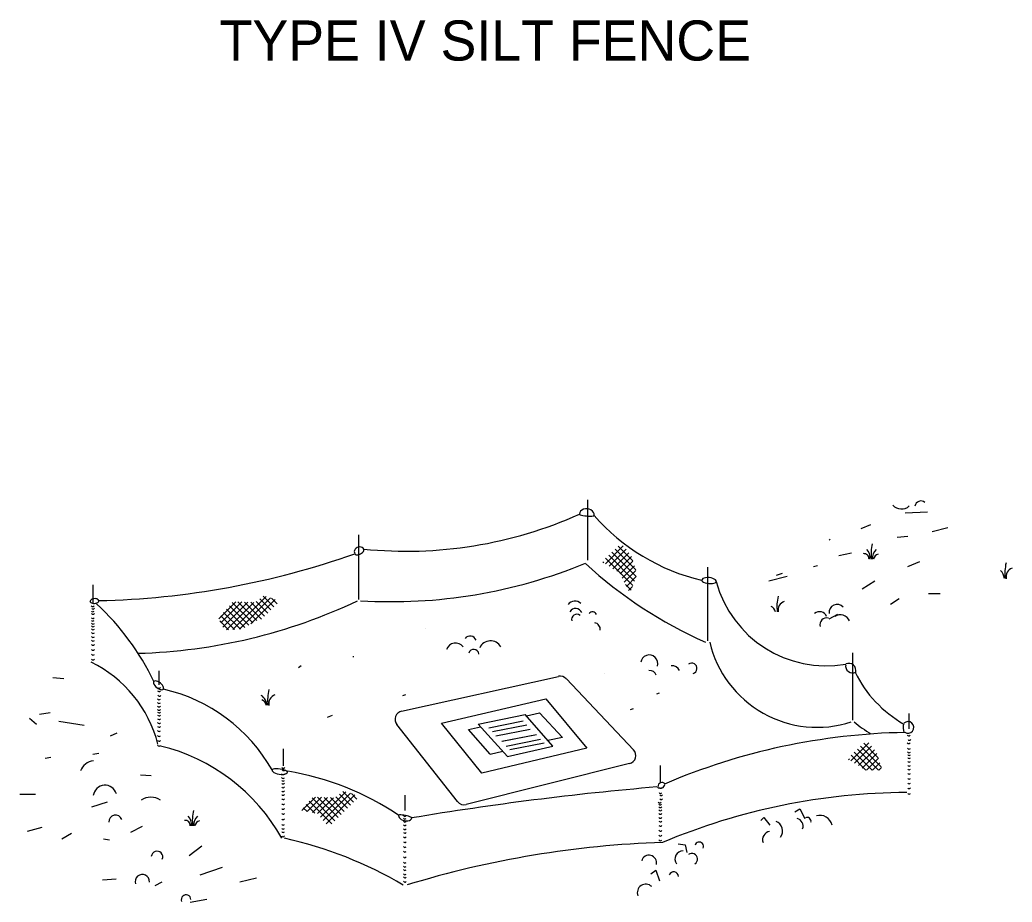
# Model space of a CAD drawing. Extents: x 539344 to 540004, y 1574686 to 1575110.
# Drawn here: x 539459.9 to 539578.4, y 1574893.2 to 1574998.7 of the extents above; entities that cross this region are included whole.
import ezdxf

# ---------------------------------------------------------------- set-up
doc = ezdxf.new("R2010")
doc.units = 0
doc.layers.add('Default', color=7, linetype='Continuous')
doc.layers.add('TextLabel', color=7, linetype='Continuous')

msp = doc.modelspace()

# ---------------------------------------------------------------- linework, layer by layer
at = {"layer": 'Default'}
for p, q in [((539527.75, 1574934.14), (539527.75, 1574941.35)), ((539565.65, 1574939.8), (539568.33, 1574939.91)), ((539560.42, 1574937.93), (539561.58, 1574938.4)), ((539568.91, 1574937.58), (539570.77, 1574938.05)), ((539500.38, 1574929.43), (539500.38, 1574937.18)), ((539556.58, 1574936.54), (539556.69, 1574936.65)), ((539564.72, 1574936.89), (539566, 1574937)), ((539531.99, 1574935.85), (539529.84, 1574933.7)), ((539532.33, 1574935.44), (539530.3, 1574933.41)), ((539530.62, 1574935.09), (539533.52, 1574932.19)), ((539532.66, 1574935.03), (539530.75, 1574933.12)), ((539531, 1574935.45), (539533.47, 1574932.98)), ((539531.38, 1574935.81), (539533.12, 1574934.07)), ((539557.74, 1574934.68), (539559.25, 1574935.02)), ((539529.55, 1574933.94), (539529.66, 1574933.82)), ((539529.86, 1574934.36), (539533.13, 1574931.1)), ((539530.24, 1574934.72), (539533.32, 1574931.64)), ((539532.96, 1574934.59), (539531.2, 1574932.83)), ((539533.14, 1574934.02), (539531.61, 1574932.5)), ((539566, 1574933.4), (539567.4, 1574933.98)), ((539533.32, 1574933.46), (539531.86, 1574932)), ((539533.5, 1574932.9), (539532.1, 1574931.51)), ((539542.08, 1574924.5), (539542.08, 1574933.32)), ((539550.29, 1574932.35), (539550.99, 1574932.58)), ((539554.72, 1574933.4), (539555.18, 1574933.51)), ((539533.52, 1574932.18), (539532.35, 1574931.01)), ((539549.36, 1574931.65), (539551.57, 1574932.23)), ((539560.53, 1574930.72), (539562.05, 1574931.65)), ((539468.64, 1574929), (539468.64, 1574931.19)), ((539532.24, 1574931.24), (539532.93, 1574930.55)), ((539533.1, 1574931.01), (539532.6, 1574930.52)), ((539485.68, 1574929.16), (539483.64, 1574927.12)), ((539486.4, 1574929.14), (539483.89, 1574926.63)), ((539487.12, 1574929.11), (539484.14, 1574926.14)), ((539487.84, 1574929.09), (539484.56, 1574925.81)), ((539485.27, 1574929.08), (539487.7, 1574926.64)), ((539489.3, 1574929.81), (539485.33, 1574925.84)), ((539485.94, 1574929.15), (539488.18, 1574926.91)), ((539489.85, 1574929.62), (539486.11, 1574925.88)), ((539486.71, 1574929.13), (539488.76, 1574927.08)), ((539487.47, 1574929.1), (539489.13, 1574927.45)), ((539490.4, 1574929.43), (539487.5, 1574926.53)), ((539488.12, 1574929.19), (539489.5, 1574927.82)), ((539488.55, 1574929.51), (539489.87, 1574928.19)), ((539488.97, 1574929.83), (539490.24, 1574928.56)), ((539489.97, 1574929.58), (539490.61, 1574928.93)), ((539563.91, 1574928.86), (539564.96, 1574929.56)), ((539568.45, 1574930.14), (539569.84, 1574930.14)), ((539484.23, 1574927.89), (539486.24, 1574925.88)), ((539484.58, 1574928.29), (539486.76, 1574926.1)), ((539484.92, 1574928.68), (539487.23, 1574926.37)), ((539483.76, 1574926.88), (539484.82, 1574925.82)), ((539483.88, 1574927.5), (539485.53, 1574925.85)), ((539556.58, 1574927.11), (539557.62, 1574927.69)), ((539508.4, 1574925.95), (539508.4, 1574925.95)), ((539559.41, 1574915.01), (539559.41, 1574923.08)), ((539499.79, 1574922.57), (539499.68, 1574922.57)), ((539476.53, 1574919.23), (539476.53, 1574920.91)), ((539493.16, 1574921.29), (539493.51, 1574921.53)), ((539463.84, 1574920.13), (539465.12, 1574920.01)), ((539505.5, 1574916.09), (539524.24, 1574920.25)), ((539525.18, 1574919.96), (539533.21, 1574911.47)), ((539529.7, 1574920.6), (539529.7, 1574920.6)), ((539505.96, 1574918.04), (539505.61, 1574917.92)), ((539510.25, 1574914.67), (539522.74, 1574917.56)), ((539522.74, 1574917.56), (539527.64, 1574911.65)), ((539535.98, 1574918.15), (539536.33, 1574918.27)), ((539462.21, 1574915.71), (539463.49, 1574915.94)), ((539532.84, 1574916.29), (539533.19, 1574916.41)), ((539461.04, 1574915.24), (539461.86, 1574914.55)), ((539464.53, 1574914.89), (539467.56, 1574914.43)), ((539496.65, 1574915.36), (539497.23, 1574915.59)), ((539514.65, 1574914.54), (539520.25, 1574915.7)), ((539515.92, 1574914.11), (539520.03, 1574914.92)), ((539523.56, 1574911.92), (539520.25, 1574915.7)), ((539520.41, 1574915.52), (539521.96, 1574915.87)), ((539524.74, 1574912.92), (539521.96, 1574915.87)), ((539566.16, 1574913.97), (539566.16, 1574915.81)), ((539512.18, 1574905.27), (539504.93, 1574914.5)), ((539515.1, 1574908.66), (539510.25, 1574914.67)), ((539513.47, 1574913.9), (539514.94, 1574914.22)), ((539516.07, 1574910.96), (539513.47, 1574913.9)), ((539518.14, 1574910.68), (539514.65, 1574914.54)), ((539516.36, 1574913.67), (539520.47, 1574914.47)), ((539516.75, 1574913.13), (539520.86, 1574913.94)), ((539470.7, 1574913.15), (539471.52, 1574913.5)), ((539517.49, 1574912.5), (539521.6, 1574913.3)), ((539517.51, 1574912.5), (539521.62, 1574913.3)), ((539517.98, 1574911.91), (539522.09, 1574912.72)), ((539524.74, 1574912.92), (539522.97, 1574912.59)), ((539491.37, 1574909.53), (539491.37, 1574911.59)), ((539527.64, 1574911.65), (539515.1, 1574908.66)), ((539516.07, 1574910.96), (539517.59, 1574911.29)), ((539518.14, 1574910.68), (539523.56, 1574911.92)), ((539518.43, 1574911.49), (539522.54, 1574912.3)), ((539561.33, 1574912.3), (539559.18, 1574910.15)), ((539561.66, 1574911.89), (539559.63, 1574909.86)), ((539559.96, 1574911.53), (539562.46, 1574909.03)), ((539562, 1574911.48), (539560.08, 1574909.57)), ((539560.33, 1574911.9), (539562.8, 1574909.43)), ((539560.71, 1574912.26), (539562.45, 1574910.52)), ((539462.91, 1574910.47), (539463.6, 1574910.59)), ((539468.61, 1574910.94), (539469.31, 1574911.05)), ((539558.88, 1574910.38), (539558.99, 1574910.27)), ((539559.2, 1574910.81), (539560.97, 1574909.03)), ((539559.58, 1574911.17), (539561.71, 1574909.03)), ((539562.29, 1574911.03), (539560.53, 1574909.27)), ((539562.47, 1574910.47), (539561.03, 1574909.03)), ((539532.73, 1574909.81), (539513.21, 1574904.92)), ((539536.42, 1574907.61), (539536.42, 1574909.57)), ((539562.65, 1574909.91), (539561.78, 1574909.03)), ((539562.83, 1574909.35), (539562.52, 1574909.03)), ((539474.31, 1574908.49), (539475.59, 1574908.38)), ((539498.82, 1574906.46), (539495.79, 1574903.43)), ((539498.49, 1574906.48), (539499.76, 1574905.21)), ((539459.88, 1574906.17), (539461.74, 1574906.17)), ((539495.2, 1574905.81), (539493.59, 1574904.2)), ((539495.92, 1574905.79), (539494.21, 1574904.08)), ((539494.44, 1574905.33), (539497.16, 1574902.61)), ((539494.79, 1574905.73), (539497.53, 1574902.98)), ((539496.64, 1574905.76), (539494.84, 1574903.96)), ((539497.36, 1574905.74), (539495.45, 1574903.84)), ((539495.46, 1574905.8), (539497.91, 1574903.36)), ((539499.37, 1574906.27), (539496.13, 1574903.03)), ((539496.23, 1574905.78), (539498.28, 1574903.73)), ((539499.92, 1574906.08), (539496.47, 1574902.63)), ((539496.99, 1574905.75), (539498.65, 1574904.1)), ((539497.64, 1574905.84), (539499.02, 1574904.47)), ((539498.07, 1574906.16), (539499.39, 1574904.84)), ((539499.49, 1574906.23), (539500.13, 1574905.58)), ((539505.91, 1574904.19), (539505.91, 1574906.05)), ((539468.49, 1574904.65), (539470.35, 1574905.24)), ((539493.75, 1574904.54), (539494.21, 1574904.08)), ((539494.1, 1574904.94), (539495.12, 1574903.91)), ((539552.5, 1574904.07), (539553.09, 1574904.42)), ((539553.09, 1574904.42), (539553.67, 1574903.26)), ((539548.43, 1574903.03), (539548.78, 1574903.37)), ((539548.78, 1574903.37), (539549.48, 1574902.44)), ((539460.81, 1574901.75), (539462.56, 1574902.21)), ((539473.15, 1574901.63), (539474.54, 1574902.33)), ((539464.88, 1574900.81), (539466.05, 1574901.51)), ((539469.89, 1574900.81), (539470.59, 1574900.7)), ((539480.13, 1574898.84), (539481.64, 1574900)), ((539538.54, 1574900.23), (539539.36, 1574900.12)), ((539539.36, 1574900.12), (539539.59, 1574899.19)), ((539481.41, 1574896.51), (539484.08, 1574897.44)), ((539535.28, 1574896.63), (539535.86, 1574897.09)), ((539535.86, 1574897.09), (539536.33, 1574895.81)), ((539469.77, 1574895.93), (539471.4, 1574896.04)), ((539486.18, 1574895.69), (539488.16, 1574896.16)), ((539476.05, 1574895.23), (539476.87, 1574895.69)), ((539480.24, 1574893.25), (539482.22, 1574893.6))]:
    msp.add_line(p, q, dxfattribs=at)
for centre, radius, start, end in [((539567.56, 1574940.47), 0.748, 50.6366, 169.3296), ((539565.23, 1574941.66), 1.4, 221.8186, 311.8186), ((539506.03, 1574985.91), 50.7, 264.2704, 294.1119), ((539546.97, 1574955.61), 24.52, 221.1263, 256.7442), ((539567.08, 1574934.87), 5.49, 166.9838, 186.4492), ((539560.73, 1574934.3), 0.621, 356.1525, 95.6419), ((539559.98, 1574934.41), 1.51, 354.036, 42.1941), ((539563.2, 1574934.37), 1.44, 134.0218, 184.6697), ((539467.12, 1575027.5), 98.22, 271.2713, 289.4914), ((539504.29, 1574989.88), 60.7, 266.5, 292.4426), ((539563.68, 1574973.26), 53.61, 227.5042, 245.9018), ((539562.67, 1574934.12), 0.782, 106.1258, 170.1309), ((539583.07, 1574932.57), 5.49, 166.9838, 186.4492), ((539575.83, 1574931.74), 1.7, 6.9894, 43.2163), ((539578.83, 1574932.14), 1.11, 109.8004, 191.1102), ((539556.22, 1574935.11), 13.6, 195.0648, 279.9146), ((539472.17, 1574988.59), 65.61, 271.6049, 295.3312), ((539526.2, 1574928.22), 1.03, 45.8458, 142.3307), ((539555.83, 1574928.59), 5.49, 166.9838, 186.4492), ((539551.59, 1574928.16), 1.11, 109.8004, 191.1102), ((539468.58, 1574928.79), 0.201, 209.3925, 323.8148), ((539468.6, 1574928.18), 0.201, 209.3925, 323.8148), ((539468.64, 1574928.5), 0.201, 209.3925, 323.8148), ((539448.35, 1574906.49), 30.52, 25.4833, 47.2792), ((539526.29, 1574927.56), 0.801, 22.2509, 149.0252), ((539528.32, 1574927.47), 0.496, 19.5572, 146.1768), ((539549.34, 1574927.82), 0.844, 9.5904, 69.4639), ((539555.45, 1574927.09), 0.89, 21.4734, 132.5198), ((539557.53, 1574927.91), 0.944, 40.415, 189.5884), ((539468.6, 1574927.36), 0.201, 209.3925, 323.8148), ((539468.6, 1574927.05), 0.201, 209.3925, 323.8148), ((539468.62, 1574927.87), 0.201, 209.3925, 323.8148), ((539526.43, 1574927.04), 0.627, 52.125, 195.2551), ((539528.46, 1574925.88), 0.776, 351.7969, 82.0054), ((539556.27, 1574926.43), 0.8, 74.0792, 195.9208), ((539557.92, 1574926.44), 1.18, 21.2965, 123.9769), ((539468.62, 1574926.69), 0.201, 209.3925, 323.8148), ((539468.62, 1574926.38), 0.201, 209.3925, 323.8148), ((539468.62, 1574926.02), 0.201, 209.3925, 323.8148), ((539468.62, 1574925.58), 0.201, 209.3925, 323.8148), ((539468.62, 1574925.11), 0.201, 209.3925, 323.8148), ((539468.62, 1574924.67), 0.201, 209.3925, 323.8148), ((539513.67, 1574924.3), 0.77, 20.2635, 140.7978), ((539516.12, 1574923.06), 1.43, 30.5601, 154.4229), ((539555.16, 1574927.36), 13.2, 193.2831, 287.9059), ((539468.62, 1574924.16), 0.201, 209.3925, 323.8148), ((539468.62, 1574923.56), 0.201, 209.3925, 323.8148), ((539511.95, 1574923.09), 1.14, 37.8709, 161.0162), ((539514.11, 1574922.85), 0.619, 6.0711, 163.5315), ((539461.72, 1574908.36), 15.14, 14.4282, 63.7692), ((539468.62, 1574922.99), 0.201, 209.3925, 323.8148), ((539468.62, 1574922.41), 0.201, 209.3925, 323.8148), ((539535.08, 1574921.79), 1.02, 342.6112, 172.3067), ((539535.17, 1574920.14), 0.8, 17.6711, 98.3533), ((539537.87, 1574920.63), 0.874, 20.5809, 101.3099), ((539540.17, 1574921.21), 0.627, 285.2308, 127.8159), ((539559.37, 1574921.49), 0.823, 169.307, 297.603), ((539558.92, 1574920.94), 0.866, 344.9997, 114.1316), ((539572.73, 1574927.19), 14.56, 206.2944, 240.2561), ((539524.45, 1574919.28), 1, 43.4045, 102.5237), ((539476.51, 1574918.63), 0.201, 209.3925, 323.8148), ((539476.53, 1574919.02), 0.201, 209.3925, 323.8148), ((539472.65, 1574899.26), 19.94, 29.4453, 77.3064), ((539494.98, 1574917.42), 5.49, 166.9838, 186.4492), ((539476.51, 1574917.65), 0.201, 209.3925, 323.8148), ((539476.55, 1574918.08), 0.201, 209.3925, 323.8148), ((539487.73, 1574916.6), 1.7, 6.9894, 53.8757), ((539488.49, 1574916.65), 0.844, 9.5904, 69.4639), ((539490.73, 1574916.99), 1.11, 109.8004, 191.1102), ((539476.51, 1574917.22), 0.201, 209.3925, 323.8148), ((539476.51, 1574916.79), 0.201, 209.3925, 323.8148), ((539476.51, 1574916.39), 0.201, 209.3925, 323.8148), ((539476.52, 1574916.08), 0.201, 209.3925, 323.8148), ((539505.72, 1574915.11), 1, 102.5229, 218.1397), ((539476.52, 1574915.72), 0.201, 209.3925, 323.8148), ((539476.52, 1574915.28), 0.201, 209.3925, 323.8148), ((539568.52, 1574925.43), 13.9, 229.9052, 240.0298), ((539566.01, 1574914.14), 0.693, 234.7925, 134.7168), ((539476.52, 1574914.81), 0.201, 209.3925, 323.8148), ((539476.52, 1574914.37), 0.201, 209.3925, 323.8148), ((539476.52, 1574913.86), 0.201, 209.3925, 323.8148), ((539567.7, 1574914.18), 2.27, 170.0354, 196.5746), ((539476.52, 1574913.26), 0.201, 209.3925, 323.8148), ((539476.52, 1574912.69), 0.201, 209.3925, 323.8148), ((539567.02, 1574836.99), 76.56, 91.0489, 113.1754), ((539566.09, 1574913.33), 0.201, 209.3925, 323.8148), ((539566.18, 1574912.8), 0.201, 209.3925, 323.8148), ((539476.52, 1574912.11), 0.201, 209.3925, 323.8148), ((539471.32, 1574889.82), 22.74, 29.1555, 76.3774), ((539532.49, 1574910.78), 1, 284.0719, 43.4024), ((539566.09, 1574912.41), 0.201, 209.3925, 323.8148), ((539566.13, 1574911.75), 0.201, 209.3925, 323.8148), ((539566.13, 1574911.31), 0.201, 209.3925, 323.8148), ((539468.92, 1574908.25), 1.93, 97.697, 158.6536), ((539566.14, 1574910.99), 0.201, 209.3925, 323.8148), ((539566.14, 1574910.63), 0.201, 209.3925, 323.8148), ((539566.14, 1574910.2), 0.201, 209.3925, 323.8148), ((539491.37, 1574909.46), 0.201, 209.3925, 323.8148), ((539491.4, 1574909.18), 0.201, 209.3925, 323.8148), ((539486.35, 1574875.78), 33.6, 55.9783, 80.4814), ((539566.14, 1574909.72), 0.201, 209.3925, 323.8148), ((539566.14, 1574909.28), 0.201, 209.3925, 323.8148), ((539491.34, 1574908.7), 0.201, 209.3925, 323.8148), ((539491.34, 1574908.25), 0.201, 209.3925, 323.8148), ((539491.35, 1574907.93), 0.201, 209.3925, 323.8148), ((539566.14, 1574908.77), 0.201, 209.3925, 323.8148), ((539566.14, 1574908.17), 0.201, 209.3925, 323.8148), ((539470.06, 1574905.82), 1.41, 15.8758, 173.2754), ((539491.35, 1574907.58), 0.201, 209.3925, 323.8148), ((539491.35, 1574907.14), 0.201, 209.3925, 323.8148), ((539491.35, 1574906.67), 0.201, 209.3925, 323.8148), ((539567.02, 1574544.29), 364.06, 94.8887, 99.5378), ((539536.44, 1574907.41), 0.534, 228.4251, 350.1144), ((539536.59, 1574907.1), 0.461, 34.692, 185.7133), ((539536.48, 1574907.07), 0.201, 209.3925, 323.8148), ((539566.14, 1574907.6), 0.201, 209.3925, 323.8148), ((539566.14, 1574907.03), 0.201, 209.3925, 323.8148), ((539475.53, 1574903.8), 2, 54.699, 125.301), ((539491.35, 1574906.23), 0.201, 209.3925, 323.8148), ((539491.35, 1574905.72), 0.201, 209.3925, 323.8148), ((539512.96, 1574905.89), 1, 218.1416, 284.0727), ((539536.43, 1574906.46), 0.201, 209.3925, 323.8148), ((539536.52, 1574906.19), 0.201, 209.3925, 323.8148), ((539536.52, 1574905.71), 0.201, 209.3925, 323.8148), ((539566.13, 1574830.83), 75.53, 90.2105, 112.9637), ((539566.14, 1574906.37), 0.201, 209.3925, 323.8148), ((539485.98, 1574902.99), 5.49, 166.9838, 186.4492), ((539491.35, 1574905.12), 0.201, 209.3925, 323.8148), ((539491.35, 1574904.55), 0.201, 209.3925, 323.8148), ((539536.34, 1574905.31), 0.201, 209.3925, 323.8148), ((539536.4, 1574905.07), 0.201, 209.3925, 323.8148), ((539536.41, 1574904.75), 0.201, 209.3925, 323.8148), ((539536.41, 1574904.39), 0.201, 209.3925, 323.8148), ((539471.32, 1574902.87), 0.793, 19.2092, 184.9244), ((539479.63, 1574902.41), 0.621, 356.1525, 95.6419), ((539478.88, 1574902.53), 1.51, 354.036, 42.1941), ((539482.1, 1574902.49), 1.44, 134.0218, 184.6697), ((539481.56, 1574902.24), 0.782, 106.1258, 170.1309), ((539491.35, 1574903.97), 0.201, 209.3925, 323.8148), ((539491.35, 1574903.32), 0.201, 209.3925, 323.8148), ((539505.89, 1574903.71), 0.201, 209.3925, 323.8148), ((539505.89, 1574903.39), 0.201, 209.3925, 323.8148), ((539505.89, 1574903.03), 0.201, 209.3925, 323.8148), ((539536.41, 1574903.96), 0.201, 209.3925, 323.8148), ((539536.41, 1574903.48), 0.201, 209.3925, 323.8148), ((539536.41, 1574903.05), 0.201, 209.3925, 323.8148), ((539549.82, 1574901.77), 1.21, 322.6795, 70.0597), ((539552.58, 1574902.36), 0.896, 338.3847, 78.8761), ((539553.94, 1574902.92), 0.475, 345.6226, 114.8688), ((539555.49, 1574902.16), 1.47, 12.0989, 106.9888), ((539491.35, 1574902.66), 0.201, 209.3925, 323.8148), ((539491.35, 1574902.19), 0.201, 209.3925, 323.8148), ((539505.89, 1574902.6), 0.201, 209.3925, 323.8148), ((539505.89, 1574902.12), 0.201, 209.3925, 323.8148), ((539536.41, 1574902.53), 0.201, 209.3925, 323.8148), ((539536.41, 1574901.94), 0.201, 209.3925, 323.8148), ((539491.35, 1574901.79), 0.201, 209.3925, 323.8148), ((539491.35, 1574901.28), 0.201, 209.3925, 323.8148), ((539480.87, 1574853.1), 48.96, 59.5236, 77.4564), ((539505.89, 1574901.69), 0.201, 209.3925, 323.8148), ((539505.89, 1574901.17), 0.201, 209.3925, 323.8148), ((539536.41, 1574901.36), 0.201, 209.3925, 323.8148), ((539536.41, 1574900.79), 0.201, 209.3925, 323.8148), ((539549.64, 1574900.71), 1.01, 100.3522, 199.1619), ((539476.27, 1574898.66), 0.687, 337.4927, 174.4961), ((539505.89, 1574900.58), 0.201, 209.3925, 323.8148), ((539505.89, 1574900), 0.201, 209.3925, 323.8148), ((539540.22, 1574784.63), 115.8, 91.7583, 107.111), ((539539.11, 1574898.43), 0.955, 89.138, 217.7617), ((539541.06, 1574899.91), 0.522, 338.9201, 164.21), ((539505.89, 1574899.43), 0.201, 209.3925, 323.8148), ((539505.89, 1574898.77), 0.201, 209.3925, 323.8148), ((539535.06, 1574897.96), 0.906, 345.9484, 165.9484), ((539540.18, 1574898.41), 0.671, 303.471, 126.492), ((539505.89, 1574898.12), 0.201, 209.3925, 323.8148), ((539505.89, 1574897.64), 0.201, 209.3925, 323.8148), ((539505.89, 1574897.25), 0.201, 209.3925, 323.8148), ((539474.52, 1574895.72), 0.851, 355.5316, 199.6667), ((539505.89, 1574896.73), 0.201, 209.3925, 323.8148), ((539505.89, 1574896.36), 0.201, 209.3925, 323.8148), ((539538, 1574896.3), 0.574, 0.7848, 156.5953), ((539505.89, 1574895.84), 0.201, 209.3925, 323.8148), ((539534.67, 1574894.39), 1.01, 45.002, 202.3621), ((539479.74, 1574893.56), 0.571, 0.5175, 202.1224)]:
    msp.add_arc(centre, radius, start, end, dxfattribs=at)
for centre, major_axis, ratio in [((539527.62, 1574939.56), (0.882, -0.077), 0.812659), ((539527.62, 1574939.56), (-0.882, 0.077), 0.149523), ((539500.43, 1574935.19), (0.537, 0.278), 0.844762), ((539500.43, 1574935.19), (-0.539, -0.277), 0.57036), ((539542.22, 1574931.66), (-0.868, 0.084), 0.361788), ((539542.22, 1574931.66), (0.868, -0.084), 0.452876), ((539468.78, 1574929.23), (0.517, 0.074), 0.590667), ((539468.8, 1574929.27), (-0.529, -0.035), 0.5856), ((539476.46, 1574919.17), (-0.568, 0.45), 0.477392), ((539476.46, 1574919.17), (0.568, -0.45), 0.48073), ((539490.94, 1574908.93), (-0.929, 0.139), 0.413696), ((539490.94, 1574908.93), (0.929, -0.139), 0.249623), ((539505.93, 1574903.47), (-0.785, 0.154), 0.604636), ((539505.92, 1574903.47), (0.776, -0.155), 0.180863)]:
    msp.add_ellipse(centre, major_axis=major_axis, ratio=ratio, start_param=0, end_param=3.141593, dxfattribs=at)

# ---------------------------------------------------------------- texts
at = {"layer": 'TextLabel'}
msp.add_text('TYPE IV SILT FENCE', height=4.8, dxfattribs=at).set_placement((539483.75, 1574993.87))

doc.saveas('drawing.dxf')
